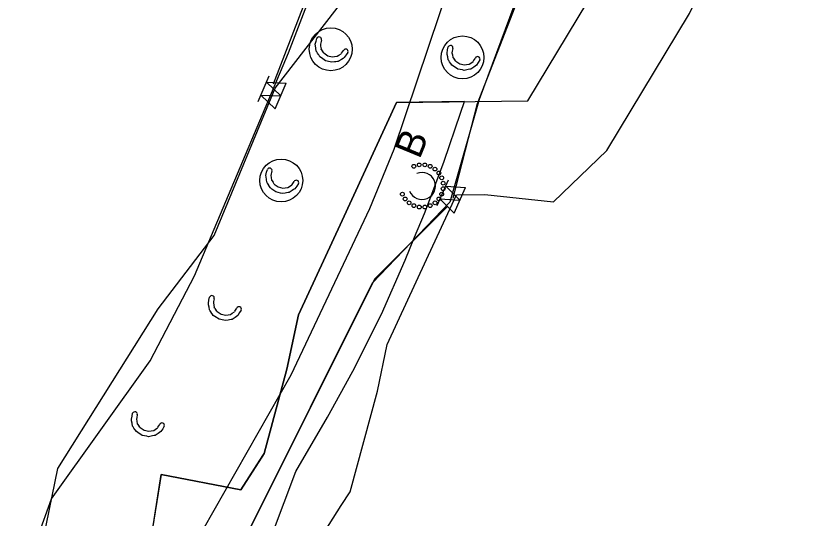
# Model space of a CAD drawing. Extents: x 2470000 to 2520000, y 340000 to 380000.
# Drawn here: x 2482810.1 to 2483235.5, y 367840.9 to 368110.8 of the extents above; entities that cross this region are included whole.
import ezdxf

# ---------------------------------------------------------------- set-up
doc = ezdxf.new("R2010")
doc.units = 0
for name, color, linetype in [('Bare Soil (Coastal) Drainage Area Border CandG Drainage', 7, 'Continuous'), ('Bare Soil (Coastal) Drainage Area Border FG Drainage', 7, 'Continuous'), ('Coir Fiber Wattle with PAM Final CELL', 7, 'Continuous'), ('ESA Hatching CG', 7, 'Continuous'), ('Label B Final CELL', 7, 'Continuous'), ('Rock Pipe Inlet Sediment Trap Type B Final CELL', 7, 'Continuous'), ('Scratch_Level_4', 7, 'Continuous'), ('Special Sediment Control Fence Both', 7, 'Continuous'), ('Special Sediment Control Fence Section CG CELL', 7, 'Continuous'), ('Temporary Silt Fence CG', 7, 'Continuous'), ('Wattle Final CELL', 7, 'Continuous')]:
    doc.layers.add(name, color=color, linetype=linetype)

# ---------------------------------------------------------------- blocks, each defined once
blk = doc.blocks.new('B3')
at = {"layer": 'Label B Final CELL'}
blk.add_text('B', height=0.3, dxfattribs=at).set_placement((-0.1057, -0.151))

msp = doc.modelspace()

# ---------------------------------------------------------------- linework, layer by layer
at = {"layer": 'Bare Soil (Coastal) Drainage Area Border CandG Drainage'}
msp.add_lwpolyline([(2482886.45, 367953.41), (2482916.58, 367992.74), (2482949.4, 368071.88), (2482986.82, 368120.54), (2483017.82, 368208.47), (2483074.25, 368273.76), (2483121.41, 368365.22), (2483196.79, 368424.3), (2483128.64, 368254.09), (2483058.9, 368065.88), (2483043.08, 368010.64), (2483001.43, 367967.07), (2482934.61, 367833.16), (2482926.11, 367773.23), (2482882.08, 367800.67), (2482824.85, 367829.95), (2482832.71, 367867.61)], close=True, dxfattribs=at)
at = {"layer": 'Bare Soil (Coastal) Drainage Area Border FG Drainage'}
msp.add_lwpolyline([(2483105.28, 368351.85), (2483032.56, 368134.42), (2483043.77, 368130.67), (2483013.12, 368039.02), (2483000.04, 368007.11), (2482957.66, 367917.74), (2482910.53, 367834.56), (2482883.4, 367799.36), (2482821.93, 367830.89), (2482829.2, 367851.28), (2482882.14, 367925.38), (2482906.02, 367971.16), (2482956.56, 368090.81), (2483010.12, 368230.8), (2483048.76, 368327.75), (2483075.3, 368347.99), (2483081.39, 368361.25)], close=True, dxfattribs=at)
at = {"layer": 'Coir Fiber Wattle with PAM Final CELL'}
for p, q in [((2482973.77, 368096.24), (2482973.58, 368095.48)), ((2482974.16, 368097.75), (2482973.77, 368096.24)), ((2482973.58, 368095.48), (2482973.75, 368094.39)), ((2482973.75, 368094.39), (2482973.97, 368092.95)), ((2482974.1, 368092.76), (2482973.97, 368092.95)), ((2482974.1, 368092.76), (2482974.71, 368091.83)), ((2482975.37, 368090.84), (2482974.71, 368091.83)), ((2482984.93, 368090.64), (2482986.01, 368092.16)), ((2483044.44, 368091.69), (2483044.27, 368090.92)), ((2483044.77, 368093.21), (2483044.44, 368091.69)), ((2482975.37, 368090.84), (2482977.54, 368089.34)), ((2482977.55, 368089.34), (2482977.54, 368089.34)), ((2482977.55, 368089.34), (2482980, 368088.68)), ((2482980, 368088.68), (2482981.2, 368088.83)), ((2482981.2, 368088.83), (2482982.63, 368089.02)), ((2482982.63, 368089.02), (2482983.5, 368089.57)), ((2482983.5, 368089.57), (2482984.74, 368090.37)), ((2482984.93, 368090.64), (2482984.74, 368090.37)), ((2483044.27, 368090.92), (2483044.48, 368089.83)), ((2483044.48, 368089.83), (2483044.76, 368088.41)), ((2483044.9, 368088.22), (2483044.76, 368088.41)), ((2483044.9, 368088.22), (2483045.55, 368087.32)), ((2483055.81, 368086.51), (2483056.82, 368088.07)), ((2483046.24, 368086.35), (2483045.55, 368087.32)), ((2483046.24, 368086.35), (2483048.46, 368084.93)), ((2483048.47, 368084.93), (2483048.46, 368084.93)), ((2483048.47, 368084.93), (2483050.95, 368084.37)), ((2483050.95, 368084.37), (2483052.14, 368084.56)), ((2483052.14, 368084.56), (2483053.56, 368084.8)), ((2483053.56, 368084.8), (2483054.41, 368085.39)), ((2483054.41, 368085.39), (2483055.62, 368086.23)), ((2483055.81, 368086.51), (2483055.62, 368086.23)), ((2482947.23, 368025.79), (2482947.04, 368025.02)), ((2482947.04, 368025.02), (2482947.21, 368023.93)), ((2482947.21, 368023.93), (2482947.43, 368022.49)), ((2482947.62, 368027.29), (2482947.23, 368025.79)), ((2482947.56, 368022.3), (2482947.43, 368022.49)), ((2482947.56, 368022.3), (2482948.17, 368021.37)), ((2482948.83, 368020.38), (2482948.17, 368021.37)), ((2482948.83, 368020.38), (2482951, 368018.88)), ((2482956.96, 368019.11), (2482958.2, 368019.91)), ((2482958.4, 368020.18), (2482958.2, 368019.91)), ((2482958.4, 368020.18), (2482959.47, 368021.7)), ((2482951.01, 368018.88), (2482951, 368018.88)), ((2482951.01, 368018.88), (2482953.46, 368018.22)), ((2482953.46, 368018.22), (2482954.66, 368018.37)), ((2482954.66, 368018.37), (2482956.09, 368018.56)), ((2482956.09, 368018.56), (2482956.96, 368019.11))]:
    msp.add_line(p, q, dxfattribs=at)
for points in [[(2482988.37, 368091.08), (2482987.49, 368089.79), (2482986.46, 368088.29), (2482985.76, 368087.84), (2482984.91, 368087.29), (2482983.4, 368086.32), (2482983.36, 368086.31), (2482982.93, 368086.25), (2482982.85, 368086.23), (2482981.9, 368086.09), (2482981.25, 368085.99), (2482979.8, 368085.78), (2482978.79, 368086.02), (2482976.31, 368086.63), (2482976.3, 368086.64), (2482974.15, 368088.17), (2482973.31, 368088.76), (2482972.71, 368089.72), (2482972.59, 368089.92), (2482972.08, 368090.74), (2482971.69, 368091.36), (2482971.6, 368091.51), (2482971.41, 368091.82), (2482971.41, 368091.83), (2482971.19, 368093.32), (2482971, 368094.65), (2482970.88, 368095.45), (2482971.3, 368097.16), (2482971.66, 368098.66)], [(2483059.22, 368087.08), (2483058.39, 368085.76), (2483057.42, 368084.22), (2483056.74, 368083.74), (2483055.91, 368083.16), (2483054.44, 368082.14), (2483054.4, 368082.13), (2483053.96, 368082.05), (2483053.89, 368082.03), (2483052.95, 368081.85), (2483052.29, 368081.73), (2483050.85, 368081.46), (2483049.83, 368081.67), (2483047.34, 368082.18), (2483047.33, 368082.19), (2483045.12, 368083.63), (2483044.26, 368084.2), (2483043.63, 368085.14), (2483043.49, 368085.33), (2483042.95, 368086.13), (2483042.55, 368086.73), (2483042.45, 368086.88), (2483042.25, 368087.18), (2483042.24, 368087.19), (2483041.97, 368088.67), (2483041.73, 368089.99), (2483041.59, 368090.79), (2483041.93, 368092.51), (2483042.24, 368094.03)], [(2482961.83, 368020.62), (2482960.95, 368019.33), (2482959.92, 368017.84), (2482959.22, 368017.38), (2482958.37, 368016.84), (2482956.86, 368015.86), (2482956.82, 368015.86), (2482956.39, 368015.79), (2482956.31, 368015.78), (2482955.37, 368015.64), (2482954.71, 368015.54), (2482953.26, 368015.32), (2482952.25, 368015.57), (2482949.77, 368016.18), (2482949.76, 368016.18), (2482947.61, 368017.71), (2482946.77, 368018.3), (2482946.17, 368019.27), (2482946.05, 368019.47), (2482945.54, 368020.28), (2482945.16, 368020.9), (2482945.07, 368021.05), (2482944.87, 368021.36), (2482944.87, 368021.37), (2482944.65, 368022.86), (2482944.46, 368024.19), (2482944.35, 368024.99), (2482944.76, 368026.7), (2482945.12, 368028.21)]]:
    msp.add_lwpolyline(points, dxfattribs=at)
for centre in [(2482979.14, 368092.79), (2483049.94, 368088.44), (2482952.6, 368022.33)]:
    msp.add_circle(centre, 11.5, dxfattribs=at)
for centre, radius, start, end in [((2482972.87, 368098.11), 1.33, 344.3047, 155.4174), ((2482987.19, 368091.62), 1.3, 335.4174, 155.4174), ((2483043.47, 368093.52), 1.33, 346.4504, 157.5631), ((2483058.02, 368087.57), 1.3, 337.5631, 157.5631), ((2482946.34, 368027.65), 1.33, 344.3047, 155.4174), ((2482960.65, 368021.16), 1.3, 335.4174, 155.4174)]:
    msp.add_arc(centre, radius, start, end, dxfattribs=at)
at = {"layer": 'ESA Hatching CG'}
msp.add_lwpolyline([(2483014.53, 368064.26), (2482985.23, 368000.82), (2482961.79, 367950.04), (2482955.63, 367920.94), (2482943.34, 367875.68), (2482930.97, 367856.06), (2482888.08, 367864.28), (2482870.64, 367755.17), (2482886.24, 367710.19), (2482923.93, 367768.93), (2482960.44, 367866.05), (2482960.44, 367866.05), (2482977.45, 367895.14), (2482991.03, 367919.95), (2483006.37, 367950.4), (2483019.07, 367979.49), (2483024.21, 367991.83), (2483029.44, 368004.57), (2483031.82, 368010.68), (2483040.06, 368032.75), (2483048.75, 368058.39), (2483050.92, 368064.66)], close=True, dxfattribs=at)
at = {"layer": 'Rock Pipe Inlet Sediment Trap Type B Final CELL'}
for centre in [(2483023.8, 368029.91), (2483026.68, 368030.68), (2483029.66, 368030.68), (2483032.55, 368029.92), (2483035.13, 368028.43), (2483037.24, 368026.32), (2483038.73, 368023.74), (2483039.51, 368020.86), (2483017.63, 368014.97), (2483038.74, 368015), (2483039.51, 368017.88), (2483019.13, 368012.39), (2483021.24, 368010.29), (2483035.15, 368010.3), (2483037.25, 368012.41), (2483023.82, 368008.8), (2483026.7, 368008.03), (2483029.69, 368008.03), (2483032.57, 368008.81)]:
    msp.add_circle(centre, 1.01, dxfattribs=at)
msp.add_arc((2483028.18, 368019.36), 7.26, 202.5625, 112.5537, dxfattribs=at)
at = {"layer": 'Scratch_Level_4'}
for points in [[(2483085.04, 368065.06), (2483127.66, 368135.84), (2483168.66, 368221.22), (2483221.15, 368286.55), (2483276.76, 368377.26), (2483355.23, 368406.68), (2483371.87, 368418.81), (2483452.82, 368525.26), (2483555.67, 368592.37), (2483775.05, 368610.58), (2483826.84, 368610.97)], [(2483098.83, 368010.77), (2483127.36, 368038.42), (2483171.71, 368112.07), (2483211.24, 368194.39), (2483262.11, 368257.71), (2483310.4, 368336.47), (2483379.17, 368362.25), (2483407.24, 368382.72), (2483487.39, 368488.11), (2483572.4, 368543.59), (2483777.32, 368560.59), (2483827.22, 368560.98)], [(2482810.09, 367584.39), (2482849.56, 367643.26), (2482897.82, 367669.79), (2482895.68, 367685.54), (2482878.31, 367730.88), (2482870.64, 367755.17), (2482877, 367793.07), (2482888.08, 367864.28), (2482930.97, 367856.06), (2482942.65, 367874.61), (2482943.34, 367875.68), (2482955.63, 367920.94), (2482961.79, 367950.04), (2482985.23, 368000.82), (2483014.53, 368064.26), (2483085.04, 368065.06)], [(2482851.62, 367556.54), (2482884.32, 367605.31), (2482951.98, 367642.51), (2482944.45, 367698.02), (2482925.53, 367747.36), (2482921.94, 367758.75), (2482926.36, 367785.1), (2482929.52, 367805.43), (2482955.1, 367800.53), (2482984.81, 367847.73), (2482989.56, 367855.08), (2483004.25, 367909.2), (2483009.54, 367934.18), (2483030.63, 367979.86), (2483046.68, 368014.62), (2483061.92, 368014.79), (2483098.83, 368010.77)]]:
    msp.add_lwpolyline(points, dxfattribs=at)
at = {"layer": 'Special Sediment Control Fence Both'}
msp.add_lwpolyline([(2483042.05, 368008.46), (2483002.85, 367969.49), (2482934.73, 367833.23), (2482923.96, 367772), (2482889.27, 367749.26)], dxfattribs=at)
at = {"layer": 'Special Sediment Control Fence Section CG CELL'}
for p, q in [((2482940.21, 368064.76), (2482946.11, 368078.55)), ((2482949.41, 368060.83), (2482955.31, 368074.62)), ((2483036.25, 368008.95), (2483042.42, 368022.62)), ((2483045.36, 368004.83), (2483051.54, 368018.5))]:
    msp.add_line(p, q, dxfattribs=at)
for points in [[(2482952.36, 368067.72), (2482944.64, 368075.1), (2482955.31, 368074.62)], [(2482949.41, 368060.83), (2482941.69, 368068.21), (2482952.36, 368067.72)], [(2483048.45, 368011.67), (2483040.88, 368019.2), (2483051.54, 368018.5)], [(2483045.36, 368004.83), (2483037.79, 368012.37), (2483048.45, 368011.67)]]:
    msp.add_lwpolyline(points, dxfattribs=at)
at = {"layer": 'Temporary Silt Fence CG'}
for points in [[(2482948.39, 368074.3), (2483043.5, 368320.59), (2483017.67, 368394.38), (2483012.85, 368413.2)], [(2483044.94, 368012.83), (2483057.9, 368063.69), (2483090.26, 368146.6), (2483115.26, 368217.56)]]:
    msp.add_lwpolyline(points, dxfattribs=at)
at = {"layer": 'Wattle Final CELL'}
for p, q in [((2482916.3, 367957.27), (2482916.14, 367956.49)), ((2482916.14, 367956.49), (2482916.35, 367955.41)), ((2482916.63, 367958.78), (2482916.3, 367957.27)), ((2482916.35, 367955.41), (2482916.62, 367953.99)), ((2482916.76, 367953.79), (2482916.62, 367953.99)), ((2482916.76, 367953.79), (2482917.41, 367952.89)), ((2482918.1, 367951.92), (2482917.41, 367952.89)), ((2482918.1, 367951.92), (2482920.32, 367950.51)), ((2482926.27, 367950.96), (2482927.48, 367951.81)), ((2482927.67, 367952.08), (2482927.48, 367951.81)), ((2482927.67, 367952.08), (2482928.69, 367953.64)), ((2482920.33, 367950.51), (2482920.32, 367950.51)), ((2482920.33, 367950.51), (2482922.81, 367949.94)), ((2482922.81, 367949.94), (2482924, 367950.14)), ((2482924, 367950.14), (2482925.42, 367950.38)), ((2482925.42, 367950.38), (2482926.27, 367950.96)), ((2482875.31, 367896.4), (2482874.97, 367894.89)), ((2482874.97, 367894.89), (2482874.81, 367894.11)), ((2482874.81, 367894.11), (2482875.02, 367893.03)), ((2482875.02, 367893.03), (2482875.3, 367891.6)), ((2482875.43, 367891.41), (2482875.3, 367891.6)), ((2482875.43, 367891.41), (2482876.08, 367890.51)), ((2482876.78, 367889.54), (2482876.08, 367890.51)), ((2482876.78, 367889.54), (2482879, 367888.13)), ((2482879.01, 367888.12), (2482879, 367888.13)), ((2482879.01, 367888.12), (2482881.48, 367887.56)), ((2482881.48, 367887.56), (2482882.67, 367887.76)), ((2482882.67, 367887.76), (2482884.1, 367888)), ((2482884.1, 367888), (2482884.94, 367888.58)), ((2482884.94, 367888.58), (2482886.16, 367889.43)), ((2482886.34, 367889.7), (2482886.16, 367889.43)), ((2482886.34, 367889.7), (2482887.36, 367891.26))]:
    msp.add_line(p, q, dxfattribs=at)
for points in [[(2482931.09, 367952.65), (2482930.25, 367951.33), (2482929.28, 367949.8), (2482928.6, 367949.32), (2482927.77, 367948.74), (2482926.3, 367947.71), (2482926.26, 367947.7), (2482925.82, 367947.62), (2482925.75, 367947.61), (2482924.81, 367947.43), (2482924.16, 367947.3), (2482922.72, 367947.03), (2482921.7, 367947.24), (2482919.2, 367947.76), (2482919.19, 367947.76), (2482916.98, 367949.21), (2482916.12, 367949.77), (2482915.49, 367950.71), (2482915.35, 367950.91), (2482914.82, 367951.7), (2482914.41, 367952.31), (2482914.31, 367952.45), (2482914.11, 367952.76), (2482914.1, 367952.76), (2482913.83, 367954.25), (2482913.59, 367955.57), (2482913.45, 367956.37), (2482913.79, 367958.09), (2482914.1, 367959.61)], [(2482889.76, 367890.27), (2482888.93, 367888.95), (2482887.95, 367887.42), (2482887.27, 367886.94), (2482886.44, 367886.36), (2482884.97, 367885.33), (2482884.93, 367885.32), (2482884.5, 367885.24), (2482884.42, 367885.22), (2482883.48, 367885.05), (2482882.83, 367884.92), (2482881.39, 367884.65), (2482880.37, 367884.86), (2482877.87, 367885.38), (2482877.86, 367885.38), (2482875.66, 367886.83), (2482874.79, 367887.39), (2482874.16, 367888.33), (2482874.03, 367888.53), (2482873.49, 367889.32), (2482873.08, 367889.93), (2482872.99, 367890.07), (2482872.78, 367890.38), (2482872.78, 367890.38), (2482872.51, 367891.87), (2482872.26, 367893.19), (2482872.12, 367893.99), (2482872.47, 367895.71), (2482872.78, 367897.23)]]:
    msp.add_lwpolyline(points, dxfattribs=at)
for centre, radius, start in [((2482915.34, 367959.1), 1.33, 346.4504), ((2482929.89, 367953.15), 1.3, 337.5631), ((2482874.01, 367896.72), 1.33, 346.4504), ((2482888.56, 367890.76), 1.3, 337.5631)]:
    msp.add_arc(centre, radius, start, 157.5631, dxfattribs=at)

# ---------------------------------------------------------------- block references
at = {"layer": 'Rock Pipe Inlet Sediment Trap Type B Final CELL', "xscale": 50, "yscale": 50, "rotation": 67.56305879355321}
msp.add_blockref('B3', (2483021.85, 368041.07), dxfattribs=at)

doc.saveas('drawing.dxf')
